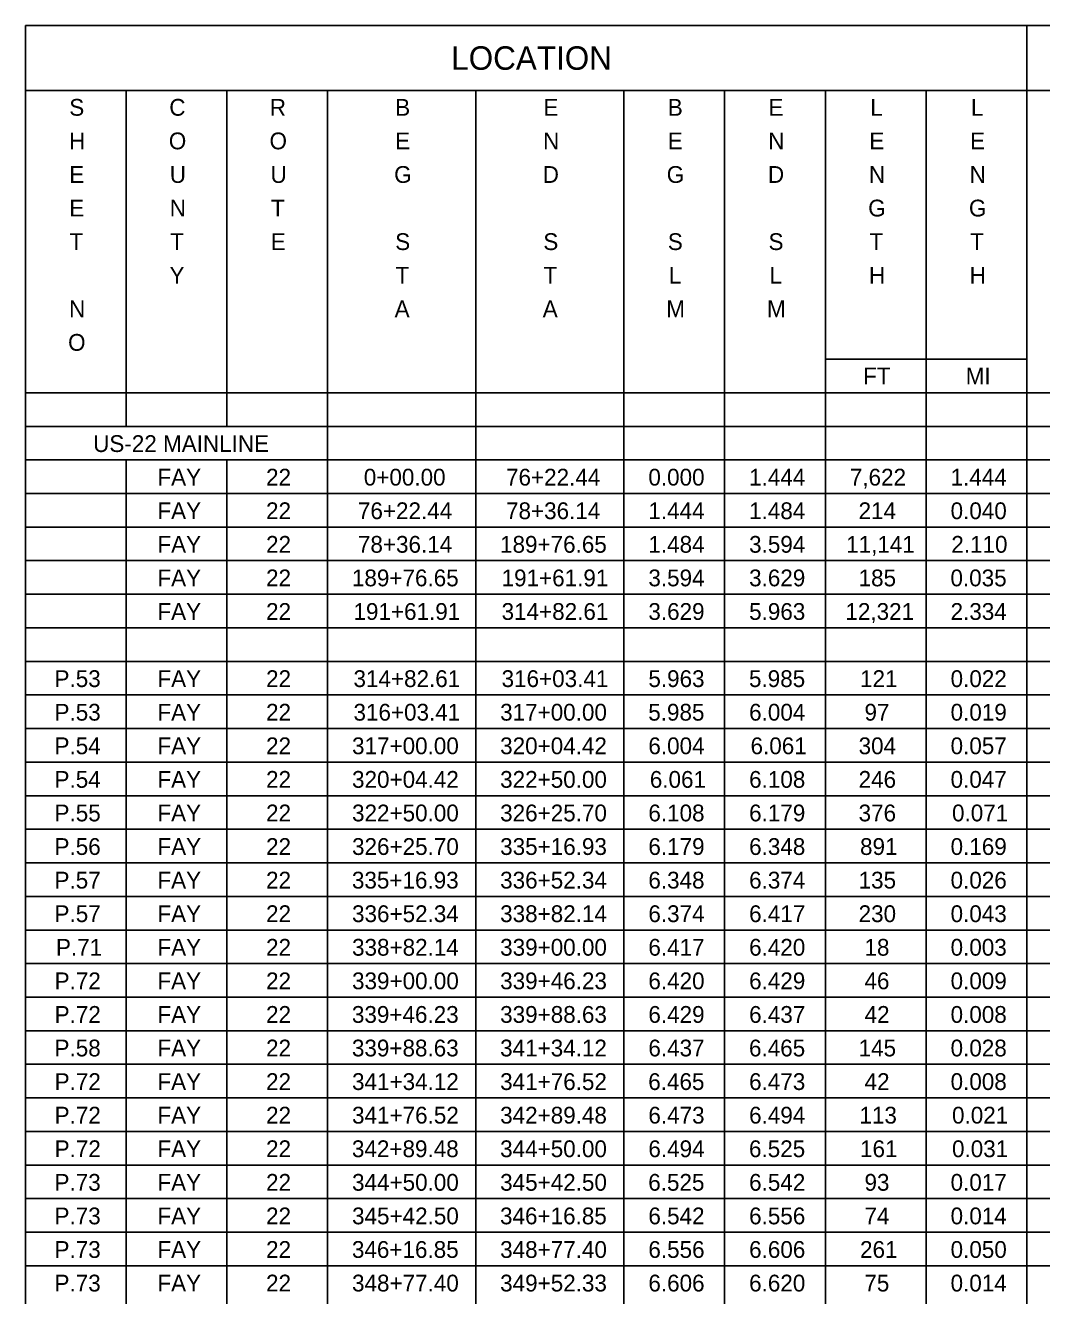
# Model space of a CAD drawing. Extents: x 12522 to 13018, y 1124 to 1902.
# Drawn here: x 12797.22 to 12805.7, y 1815.06 to 1825.65 of the extents above; entities that cross this region are included whole.
import ezdxf

# ---------------------------------------------------------------- set-up
doc = ezdxf.new("R2010")
doc.units = 0
for name, color, linetype in [('SC_Scratch1', 7, 'Continuous'), ('SH_Data', 7, 'Continuous'), ('SH_Text', 7, 'Continuous')]:
    doc.layers.add(name, color=color, linetype=linetype)

msp = doc.modelspace()

# ---------------------------------------------------------------- linework, layer by layer
at = {"layer": 'SC_Scratch1'}
msp.add_lwpolyline([(12797.224, 1825.65), (12827.724, 1825.65), (12827.724, 1804.65), (12797.224, 1804.65)], close=True, dxfattribs=at)
at = {"layer": 'SH_Data'}
for p, q in [((12805.575, 1825.65), (12805.575, 1805.227)), ((12797.224, 1825.107), (12827.678, 1825.107)), ((12798.064, 1825.107), (12798.064, 1822.307)), ((12798.904, 1825.107), (12798.904, 1822.307)), ((12799.744, 1825.107), (12799.744, 1805.227)), ((12800.979, 1825.107), (12800.979, 1805.227)), ((12802.215, 1825.107), (12802.215, 1805.227)), ((12803.055, 1825.107), (12803.055, 1805.227)), ((12803.895, 1825.107), (12803.895, 1805.227)), ((12804.735, 1825.107), (12804.735, 1805.227)), ((12803.895, 1822.867), (12805.575, 1822.867)), ((12797.224, 1822.587), (12827.678, 1822.587)), ((12797.224, 1822.307), (12827.678, 1822.307)), ((12797.224, 1822.027), (12827.678, 1822.027)), ((12798.064, 1822.027), (12798.064, 1805.227)), ((12798.904, 1822.027), (12798.904, 1805.227)), ((12797.224, 1821.747), (12827.678, 1821.747)), ((12797.224, 1821.467), (12827.678, 1821.467)), ((12797.224, 1821.187), (12827.678, 1821.187)), ((12797.224, 1820.907), (12827.678, 1820.907)), ((12797.224, 1820.627), (12827.678, 1820.627)), ((12797.224, 1820.347), (12827.678, 1820.347)), ((12797.224, 1820.067), (12827.678, 1820.067)), ((12797.224, 1819.787), (12827.678, 1819.787)), ((12797.224, 1819.507), (12827.678, 1819.507)), ((12797.224, 1819.227), (12827.678, 1819.227)), ((12797.224, 1818.947), (12827.678, 1818.947)), ((12797.224, 1818.667), (12827.678, 1818.667)), ((12797.224, 1818.387), (12827.678, 1818.387)), ((12797.224, 1818.107), (12827.678, 1818.107)), ((12797.224, 1817.827), (12827.678, 1817.827)), ((12797.224, 1817.547), (12827.678, 1817.547)), ((12797.224, 1817.267), (12827.678, 1817.267)), ((12797.224, 1816.987), (12827.678, 1816.987)), ((12797.224, 1816.707), (12827.678, 1816.707)), ((12797.224, 1816.427), (12827.678, 1816.427)), ((12797.224, 1816.147), (12827.678, 1816.147)), ((12797.224, 1815.867), (12827.678, 1815.867)), ((12797.224, 1815.587), (12827.678, 1815.587)), ((12797.224, 1815.307), (12827.678, 1815.307))]:
    msp.add_line(p, q, dxfattribs=at)

# ---------------------------------------------------------------- texts
at = {"layer": 'SH_Text'}
for s, height, p in [('LOCATION', 0.196, (12800.775, 1825.28)), ('S', 0.14, (12797.59, 1824.897)), ('C', 0.14, (12798.424, 1824.897)), ('R', 0.14, (12799.262, 1824.897)), ('B', 0.14, (12800.308, 1824.897)), ('E', 0.14, (12801.543, 1824.897)), ('B', 0.14, (12802.581, 1824.897)), ('E', 0.14, (12803.421, 1824.897)), ('L', 0.14, (12804.269, 1824.897)), ('L', 0.14, (12805.109, 1824.897)), ('H', 0.14, (12797.588, 1824.617)), ('O', 0.14, (12798.42, 1824.617)), ('O', 0.14, (12799.26, 1824.617)), ('E', 0.14, (12800.308, 1824.617)), ('N', 0.14, (12801.541, 1824.617)), ('E', 0.14, (12802.581, 1824.617)), ('N', 0.14, (12803.418, 1824.617)), ('E', 0.14, (12804.261, 1824.617)), ('E', 0.14, (12805.101, 1824.617)), ('E', 0.14, (12797.59, 1824.337)), ('U', 0.14, (12798.428, 1824.337)), ('U', 0.14, (12799.268, 1824.337)), ('G', 0.14, (12800.299, 1824.337)), ('D', 0.14, (12801.538, 1824.337)), ('G', 0.14, (12802.572, 1824.337)), ('D', 0.14, (12803.416, 1824.337)), ('N', 0.14, (12804.258, 1824.337)), ('N', 0.14, (12805.098, 1824.337)), ('E', 0.14, (12797.59, 1824.057)), ('N', 0.14, (12798.428, 1824.057)), ('T', 0.14, (12799.272, 1824.057)), ('G', 0.14, (12804.252, 1824.057)), ('G', 0.14, (12805.092, 1824.057)), ('T', 0.14, (12797.592, 1823.777)), ('T', 0.14, (12798.432, 1823.777)), ('E', 0.14, (12799.27, 1823.777)), ('S', 0.14, (12800.308, 1823.777)), ('S', 0.14, (12801.543, 1823.777)), ('S', 0.14, (12802.581, 1823.777)), ('S', 0.14, (12803.421, 1823.777)), ('T', 0.14, (12804.263, 1823.777)), ('T', 0.14, (12805.103, 1823.777)), ('Y', 0.14, (12798.426, 1823.497)), ('T', 0.14, (12800.31, 1823.497)), ('T', 0.14, (12801.545, 1823.497)), ('L', 0.14, (12802.589, 1823.497)), ('L', 0.14, (12803.429, 1823.497)), ('H', 0.14, (12804.258, 1823.497)), ('H', 0.14, (12805.098, 1823.497)), ('N', 0.14, (12797.588, 1823.217)), ('A', 0.14, (12800.303, 1823.217)), ('A', 0.14, (12801.538, 1823.217)), ('M', 0.14, (12802.568, 1823.217)), ('M', 0.14, (12803.408, 1823.217)), ('O', 0.14, (12797.58, 1822.937)), ('FT', 0.14, (12804.209, 1822.657)), ('MI', 0.14, (12805.065, 1822.657)), ('US-22 MAINLINE', 0.14, (12797.789, 1822.093)), ('FAY', 0.14, (12798.325, 1821.813)), ('22', 0.14, (12799.231, 1821.813)), ('0+00.00', 0.14, (12800.046, 1821.813)), ('76+22.44', 0.14, (12801.232, 1821.813)), ('0.000', 0.14, (12802.419, 1821.813)), ('1.444', 0.14, (12803.259, 1821.813)), ('7,622', 0.14, (12804.099, 1821.813)), ('1.444', 0.14, (12804.939, 1821.813)), ('FAY', 0.14, (12798.325, 1821.533)), ('22', 0.14, (12799.231, 1821.533)), ('76+22.44', 0.14, (12799.997, 1821.533)), ('78+36.14', 0.14, (12801.232, 1821.533)), ('1.444', 0.14, (12802.419, 1821.533)), ('1.484', 0.14, (12803.259, 1821.533)), ('214', 0.14, (12804.172, 1821.533)), ('0.040', 0.14, (12804.939, 1821.533)), ('FAY', 0.14, (12798.325, 1821.253)), ('22', 0.14, (12799.231, 1821.253)), ('78+36.14', 0.14, (12799.997, 1821.253)), ('189+76.65', 0.14, (12801.182, 1821.253)), ('1.484', 0.14, (12802.419, 1821.253)), ('3.594', 0.14, (12803.259, 1821.253)), ('11,141', 0.14, (12804.068, 1821.253)), ('2.110', 0.14, (12804.945, 1821.253)), ('FAY', 0.14, (12798.325, 1820.973)), ('22', 0.14, (12799.231, 1820.973)), ('189+76.65', 0.14, (12799.947, 1820.973)), ('191+61.91', 0.14, (12801.195, 1820.973)), ('3.594', 0.14, (12802.419, 1820.973)), ('3.629', 0.14, (12803.259, 1820.973)), ('185', 0.14, (12804.172, 1820.973)), ('0.035', 0.14, (12804.938, 1820.973)), ('FAY', 0.14, (12798.325, 1820.693)), ('22', 0.14, (12799.231, 1820.693)), ('191+61.91', 0.14, (12799.96, 1820.693)), ('314+82.61', 0.14, (12801.195, 1820.693)), ('3.629', 0.14, (12802.419, 1820.693)), ('5.963', 0.14, (12803.259, 1820.693)), ('12,321', 0.14, (12804.062, 1820.693)), ('2.334', 0.14, (12804.939, 1820.693)), ('P.53', 0.14, (12797.467, 1820.133)), ('FAY', 0.14, (12798.325, 1820.133)), ('22', 0.14, (12799.231, 1820.133)), ('314+82.61', 0.14, (12799.96, 1820.133)), ('316+03.41', 0.14, (12801.195, 1820.133)), ('5.963', 0.14, (12802.419, 1820.133)), ('5.985', 0.14, (12803.258, 1820.133)), ('121', 0.14, (12804.184, 1820.133)), ('0.022', 0.14, (12804.939, 1820.133)), ('P.53', 0.14, (12797.467, 1819.853)), ('FAY', 0.14, (12798.325, 1819.853)), ('22', 0.14, (12799.231, 1819.853)), ('316+03.41', 0.14, (12799.96, 1819.853)), ('317+00.00', 0.14, (12801.183, 1819.853)), ('5.985', 0.14, (12802.418, 1819.853)), ('6.004', 0.14, (12803.259, 1819.853)), ('97', 0.14, (12804.221, 1819.853)), ('0.019', 0.14, (12804.939, 1819.853)), ('P.54', 0.14, (12797.467, 1819.573)), ('FAY', 0.14, (12798.325, 1819.573)), ('22', 0.14, (12799.231, 1819.573)), ('317+00.00', 0.14, (12799.948, 1819.573)), ('320+04.42', 0.14, (12801.183, 1819.573)), ('6.004', 0.14, (12802.419, 1819.573)), ('6.061', 0.14, (12803.271, 1819.573)), ('304', 0.14, (12804.172, 1819.573)), ('0.057', 0.14, (12804.939, 1819.573)), ('P.54', 0.14, (12797.467, 1819.293)), ('FAY', 0.14, (12798.325, 1819.293)), ('22', 0.14, (12799.231, 1819.293)), ('320+04.42', 0.14, (12799.948, 1819.293)), ('322+50.00', 0.14, (12801.183, 1819.293)), ('6.061', 0.14, (12802.431, 1819.293)), ('6.108', 0.14, (12803.259, 1819.293)), ('246', 0.14, (12804.172, 1819.293)), ('0.047', 0.14, (12804.939, 1819.293)), ('P.55', 0.14, (12797.467, 1819.013)), ('FAY', 0.14, (12798.325, 1819.013)), ('22', 0.14, (12799.231, 1819.013)), ('322+50.00', 0.14, (12799.948, 1819.013)), ('326+25.70', 0.14, (12801.183, 1819.013)), ('6.108', 0.14, (12802.419, 1819.013)), ('6.179', 0.14, (12803.259, 1819.013)), ('376', 0.14, (12804.172, 1819.013)), ('0.071', 0.14, (12804.951, 1819.013)), ('P.56', 0.14, (12797.467, 1818.733)), ('FAY', 0.14, (12798.325, 1818.733)), ('22', 0.14, (12799.231, 1818.733)), ('326+25.70', 0.14, (12799.948, 1818.733)), ('335+16.93', 0.14, (12801.183, 1818.733)), ('6.179', 0.14, (12802.419, 1818.733)), ('6.348', 0.14, (12803.259, 1818.733)), ('891', 0.14, (12804.184, 1818.733)), ('0.169', 0.14, (12804.939, 1818.733)), ('P.57', 0.14, (12797.467, 1818.453)), ('FAY', 0.14, (12798.325, 1818.453)), ('22', 0.14, (12799.231, 1818.453)), ('335+16.93', 0.14, (12799.947, 1818.453)), ('336+52.34', 0.14, (12801.183, 1818.453)), ('6.348', 0.14, (12802.419, 1818.453)), ('6.374', 0.14, (12803.259, 1818.453)), ('135', 0.14, (12804.172, 1818.453)), ('0.026', 0.14, (12804.939, 1818.453)), ('P.57', 0.14, (12797.467, 1818.173)), ('FAY', 0.14, (12798.325, 1818.173)), ('22', 0.14, (12799.231, 1818.173)), ('336+52.34', 0.14, (12799.948, 1818.173)), ('338+82.14', 0.14, (12801.183, 1818.173)), ('6.374', 0.14, (12802.419, 1818.173)), ('6.417', 0.14, (12803.259, 1818.173)), ('230', 0.14, (12804.172, 1818.173)), ('0.043', 0.14, (12804.939, 1818.173)), ('P.71', 0.14, (12797.479, 1817.893)), ('FAY', 0.14, (12798.325, 1817.893)), ('22', 0.14, (12799.231, 1817.893)), ('338+82.14', 0.14, (12799.948, 1817.893)), ('339+00.00', 0.14, (12801.183, 1817.893)), ('6.417', 0.14, (12802.419, 1817.893)), ('6.420', 0.14, (12803.259, 1817.893)), ('18', 0.14, (12804.221, 1817.893)), ('0.003', 0.14, (12804.939, 1817.893)), ('P.72', 0.14, (12797.468, 1817.613)), ('FAY', 0.14, (12798.325, 1817.613)), ('22', 0.14, (12799.231, 1817.613)), ('339+00.00', 0.14, (12799.948, 1817.613)), ('339+46.23', 0.14, (12801.183, 1817.613)), ('6.420', 0.14, (12802.419, 1817.613)), ('6.429', 0.14, (12803.259, 1817.613)), ('46', 0.14, (12804.221, 1817.613)), ('0.009', 0.14, (12804.939, 1817.613)), ('P.72', 0.14, (12797.468, 1817.333)), ('FAY', 0.14, (12798.325, 1817.333)), ('22', 0.14, (12799.231, 1817.333)), ('339+46.23', 0.14, (12799.947, 1817.333)), ('339+88.63', 0.14, (12801.183, 1817.333)), ('6.429', 0.14, (12802.419, 1817.333)), ('6.437', 0.14, (12803.259, 1817.333)), ('42', 0.14, (12804.222, 1817.333)), ('0.008', 0.14, (12804.939, 1817.333)), ('P.58', 0.14, (12797.467, 1817.053)), ('FAY', 0.14, (12798.325, 1817.053)), ('22', 0.14, (12799.231, 1817.053)), ('339+88.63', 0.14, (12799.947, 1817.053)), ('341+34.12', 0.14, (12801.183, 1817.053)), ('6.437', 0.14, (12802.419, 1817.053)), ('6.465', 0.14, (12803.258, 1817.053)), ('145', 0.14, (12804.172, 1817.053)), ('0.028', 0.14, (12804.939, 1817.053)), ('P.72', 0.14, (12797.468, 1816.773)), ('FAY', 0.14, (12798.325, 1816.773)), ('22', 0.14, (12799.231, 1816.773)), ('341+34.12', 0.14, (12799.948, 1816.773)), ('341+76.52', 0.14, (12801.183, 1816.773)), ('6.465', 0.14, (12802.418, 1816.773)), ('6.473', 0.14, (12803.259, 1816.773)), ('42', 0.14, (12804.222, 1816.773)), ('0.008', 0.14, (12804.939, 1816.773)), ('P.72', 0.14, (12797.468, 1816.493)), ('FAY', 0.14, (12798.325, 1816.493)), ('22', 0.14, (12799.231, 1816.493)), ('341+76.52', 0.14, (12799.948, 1816.493)), ('342+89.48', 0.14, (12801.183, 1816.493)), ('6.473', 0.14, (12802.419, 1816.493)), ('6.494', 0.14, (12803.259, 1816.493)), ('113', 0.14, (12804.179, 1816.493)), ('0.021', 0.14, (12804.951, 1816.493)), ('P.72', 0.14, (12797.468, 1816.213)), ('FAY', 0.14, (12798.325, 1816.213)), ('22', 0.14, (12799.231, 1816.213)), ('342+89.48', 0.14, (12799.947, 1816.213)), ('344+50.00', 0.14, (12801.183, 1816.213)), ('6.494', 0.14, (12802.419, 1816.213)), ('6.525', 0.14, (12803.258, 1816.213)), ('161', 0.14, (12804.184, 1816.213)), ('0.031', 0.14, (12804.951, 1816.213)), ('P.73', 0.14, (12797.467, 1815.933)), ('FAY', 0.14, (12798.325, 1815.933)), ('22', 0.14, (12799.231, 1815.933)), ('344+50.00', 0.14, (12799.948, 1815.933)), ('345+42.50', 0.14, (12801.183, 1815.933)), ('6.525', 0.14, (12802.418, 1815.933)), ('6.542', 0.14, (12803.259, 1815.933)), ('93', 0.14, (12804.221, 1815.933)), ('0.017', 0.14, (12804.939, 1815.933)), ('P.73', 0.14, (12797.467, 1815.653)), ('FAY', 0.14, (12798.325, 1815.653)), ('22', 0.14, (12799.231, 1815.653)), ('345+42.50', 0.14, (12799.948, 1815.653)), ('346+16.85', 0.14, (12801.182, 1815.653)), ('6.542', 0.14, (12802.419, 1815.653)), ('6.556', 0.14, (12803.259, 1815.653)), ('74', 0.14, (12804.221, 1815.653)), ('0.014', 0.14, (12804.939, 1815.653)), ('P.73', 0.14, (12797.467, 1815.373)), ('FAY', 0.14, (12798.325, 1815.373)), ('22', 0.14, (12799.231, 1815.373)), ('346+16.85', 0.14, (12799.947, 1815.373)), ('348+77.40', 0.14, (12801.183, 1815.373)), ('6.556', 0.14, (12802.419, 1815.373)), ('6.606', 0.14, (12803.259, 1815.373)), ('261', 0.14, (12804.184, 1815.373)), ('0.050', 0.14, (12804.939, 1815.373)), ('P.73', 0.14, (12797.467, 1815.093)), ('FAY', 0.14, (12798.325, 1815.093)), ('22', 0.14, (12799.231, 1815.093)), ('348+77.40', 0.14, (12799.948, 1815.093)), ('349+52.33', 0.14, (12801.183, 1815.093)), ('6.606', 0.14, (12802.419, 1815.093)), ('6.620', 0.14, (12803.259, 1815.093)), ('75', 0.14, (12804.22, 1815.093)), ('0.014', 0.14, (12804.939, 1815.093))]:
    msp.add_text(s, height=height, dxfattribs=at).set_placement(p)

doc.saveas('drawing.dxf')
